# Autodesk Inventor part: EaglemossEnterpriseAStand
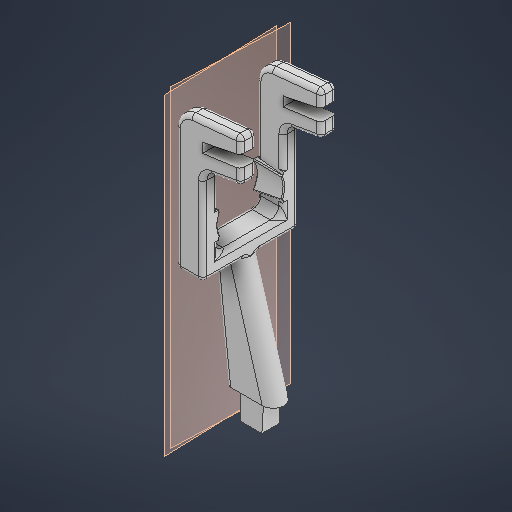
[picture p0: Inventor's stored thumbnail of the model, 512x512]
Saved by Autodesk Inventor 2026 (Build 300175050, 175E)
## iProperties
Created: 2025-11
Part Number: EaglemossEnterpriseAStand
Material: Generic
Document SubType Name: Modeling
Designer: Andrew
Density: 1 g/cm^3
Appearance: Default
Author: Andrew
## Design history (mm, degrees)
sketch "Sketch1"
  geometry: L1 (2.5, 2)-(-2.5, 2); L2 (-2.5, 2)-(-2.5, -2); L3 (-2.5, -2)-(2.5, -2); L4 (2.5, -2)-(2.5, 2); 2 further points
  constraints: 8 end point, 2 parallel, 1 horizontal, 1 midpoint, 1 perpendicular
  dimensions: "d0" = 4 distance between parallel lines of L3 L1; "d1" = 2 distance from line of point (0, 0) L1 (= 0.5 x d0); "d2" = 5 distance from line of L2 point (2.5, 0); "d3" = 2.5 distance of point (0, 0) point (2.5, 0) (= 0.5 x d2)
extrude "Extrusion1" new body sketch "Sketch1" distance "d4" = 6.2; taper "d5" = 0 deg
sketch "Sketch2"
  geometry: L1 (5, 0)-(5, 6.2) reference; L2 (5, 6.2)-(5.4, 6.2); L3 (5.4, 6.2)-(5, 0); L4 (5, 0)-(5, 6.2); 1 further point
  constraints: 6 end point, 1 collinear, 1 horizontal
  dimensions: "d6" = 0.4 distance of L1.end L2.end
extrude "Extrusion2" join sketch "Sketch2" stored distance "d7" = 6.2; taper "d8" = 0 deg
sketch "Sketch4"
  geometry: L1 (-5.3, 6.2)-(-8.3, 32.7); L2 (-8.3, 32.7)-(-2.1, 32.7); L3 (-2.1, 32.7)-(5.7, 6.2); L4 (5.7, 6.2)-(-5.3, 6.2); L5 (2.9, 6.2)-(-2.5, 6.2) reference; 2 further points
  constraints: 8 end point, 1 horizontal, 1 midpoint, 1 parallel
  dimensions: "d14" = 11 distance of L1.start L3.end; "d15" = 5.5 distance of point (0.2, 6.2) L3.end (= 0.5 x d14); "d16" = 0 distance between parallel lines of L5 L4; "d17" = 26.5 distance between parallel lines of L4 L2; "d18" = 6.2 distance of L1.end L2.end; "d19" = 3 horizontal distance of L1.start L1.end
extrude "Extrusion3" join sketch "Sketch4" stored distance "d20" = 5; taper "d21" = 0 deg
fillet "Fillet1" dims "d22" = 2.5
sketch "Sketch6"
  geometry: L1 (0, 13.75)-(6.2, 13.75); L2 (6.2, 13.75)-(6.2, -8.75); L3 (6.2, -8.75)-(0, -8.75); L4 (0, -8.75)-(0, 13.75); L5 (0, 5)-(0, 0) reference; 4 further points; 1 other entity
  constraints: 8 end point, 2 midpoint, 2 parallel, 1 horizontal, 1 perpendicular, 1 vertical, 1 other
  dimensions: "d23" = 22.5 distance between parallel lines of L3 L1; "d24" = 11.25 distance from line of point (3.594, 2.5) L1 (= 0.5 x d23)
extrude "Extrusion4" join sketch "Sketch6" distance "d25" = 4; taper "d26" = 0 deg
sketch "Sketch7"
  geometry: L1 (0, 13.75)-(0, -8.75) reference; L2 (0, 13.75)-(6.2, 13.75); L3 (6.2, 13.75)-(6.2, 10.075); L4 (6.2, 10.075)-(0, 10.075); L5 (0, 10.075)-(0, 13.75); L6 (6.2, -8.75)-(6.2, 13.75) reference; L7 (6.2, -8.75)-(0, -8.75); L8 (0, -8.75)-(0, -5.075); L9 (0, -5.075)-(6.2, -5.075); L10 (6.2, -5.075)-(6.2, -8.75); 5 further points
  constraints: 16 end point, 4 parallel, 2 horizontal, 2 perpendicular, 2 point on line
  dimensions: "d28" = 15.15 distance between parallel lines of L9 L4; "d29" = 7.575 distance from line of point (8.3, 2.5) L4 (= 0.5 x d28)
extrude "Extrusion5" join sketch "Sketch7" distance "d30" = 28.5; taper "d31" = 0 deg
sketch "Sketch9"
  geometry: L1 (6.2, 4)-(6.2, 32.5) reference; L2 (6.2, 32.5)-(15.074, 34); L3 (15.074, 34)-(15.074, 30.45); L4 (15.074, 30.45)-(6.2, 28.95); L5 (6.2, 28.95)-(6.2, 32.5); L6 (6.2, 22.561)-(15.074, 24.061); L7 (15.074, 24.061)-(15.074, 27.611); L8 (15.074, 27.611)-(6.2, 26.111); L9 (6.2, 26.111)-(6.2, 22.561); L10 (6.2, 0)-(6.2, 32.5) reference; 7 further points
  constraints: 16 end point, 5 parallel, 4 midpoint, 2 collinear, 2 point on line
  dimensions: "d33" = 9 distance of point (6.2, 30.725) point (15.074, 32.225); "d34" = 3.5 distance between parallel lines of L4 L2; "d35" = 3.5 distance between parallel lines of L6 L8; "d49" = 2.8 distance between parallel lines of L4 L8; "d50" = 1.5 vertical distance of L6.start L6.end
extrude "Extrusion6" join sketch "Sketch9" stored distance "d36" = 20; taper "d37" = 0 deg
fillet "Fillet2" dims "d38" = 2.5
chamfer "Chamfer3" distance "d51" = 0.3; stored, may be unused: second distance "d52" = 9, angle "d53" = 89 deg
chamfer "Chamfer4" distance "d54" = 0.3; stored, may be unused: second distance "d55" = 9, angle "d56" = 89 deg
sketch "Sketch10"
  geometry: L1 (0, 32.5)-(6.2, 32.5) reference; L2 (15.074, 34)-(6.2, 32.5) reference; L3 (0, 4)-(0, 32.5) reference; L4 (0, 32.5)-(15.074, 34); 2 further points
  constraints: 2 end point
extrude "Extrusion7" join sketch "Sketch10" stored distance "d57" = 10; taper "d58" = 0 deg
mirror "Mirror1"
fillet "Fillet3" dims "d45" = 4
fillet "Fillet4" dims "d46" = 1
fillet "Fillet5" dims "d47" = 1
fillet "Fillet6" dims "d59" = 2
sketch "Sketch11"
  geometry: L1 (3.825, 12.3)-(1.675, 12.3); L2 (1.675, 12.3)-(1.675, 5.8); L3 (1.675, 5.8)-(3.825, 5.8); L4 (3.825, 5.8)-(3.825, 12.3); L5 (1.675, 19.448)-(1.675, 2) reference; L6 (18.825, 2)-(18.825, 19.448) reference; L7 (15.825, 3)-(4.675, 3) reference; L8 (2.675, 5)-(2.675, 19.448) reference; L9 (17.825, 19.448)-(17.825, 5) reference; 1 further point
  constraints: 8 end point, 2 parallel, 1 horizontal, 1 perpendicular
  dimensions: "d60" = 0 distance between parallel lines of L5 L2; "d62" = 2.8 distance between parallel lines of L7 L3; "d63" = 1.15 distance between parallel lines of L4 L8; "d68" = 6.5 distance between parallel lines of L3 L1
extrude "Extrusion8" join sketch "Sketch11" stored distance "d66" = 28.5; taper "d67" = 0 deg
sketch "Sketch12"
  geometry: L1 (0, 5.75)-(6.2, 6.5); L2 (6.2, 6.5)-(6.2, 8); L3 (6.2, 8)-(-1, 8); L4 (-1, 8)-(-1, -1); L5 (-1, -1)-(6.2, -1); L6 (6.2, -1)-(6.2, 0); L7 (6.2, 0)-(0, 0.75); L8 (0, 0.75)-(0, 5.75); L9 (6.2, 6.5)-(6.2, 0); L10 (6.2, -5.8)-(6.2, 22.078) reference; L11 (0, 13.648)-(0, -5.8) reference; 1 further point
  constraints: 18 end point, 3 perpendicular, 2 point on line, 2 vertical, 1 parallel
  dimensions: "d69" = 6.5 distance of L6.end L1.end; "d70" = 5 distance of L7.end L1.start; "d71" = 0.75 vertical distance of L1.end L1.start (derived); "d72" = 6.2 distance between parallel lines of L9 L8 (derived); "d73" = 6.2 distance between parallel lines of L10 L11 (derived); "d74" = 1 distance from line of L6.end L5; "d75" = 9 distance between parallel lines of L5 L3; "d76" = 1 distance between parallel lines of L8 L4
extrude "Extrusion9" cut sketch "Sketch12" stored distance "d77" = 10; taper "d78" = 0 deg
workplane "Work Plane2"
sketch "Sketch13"
  geometry: L1 (17.203, 1.114)-(1.625, 1.114) reference; A1 r 5.296 centre (-1.625, -4.182) between (-4.875, 0) and (1.625, 0); 1 further point
  constraints: 2 point on circle, 1 centre point
  dimensions: "d80" = 0 distance edge to line of A1 L1
extrude "Extrusion10" cut sketch "Sketch13" extent not by distance; stored distance "d81" = 0; taper "d82" = 0 deg
fillet "Fillet7" dims "d83" = 0.2
mirror "Mirror2"
body "Solid1"
workplane "Work Plane1"
workplane "Work Plane3"
other parameters: "d79" = 178 deg
